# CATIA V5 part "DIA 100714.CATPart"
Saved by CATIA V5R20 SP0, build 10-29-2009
Part number: DIA 100714
Revision: ANY
Definition: UNKNOWN
Nomenclature: DIA 100714
Source: Unknown
Bounding box of the stored display mesh (mm): x -5.35 to 5.35, y -17 to 0, z -5.35 to 5.35
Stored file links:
  C:\Users\Utente\Desktop\IO LAVORO\3D X SITO CF\CUMSA\3D files FA\FA 200712-21\DIA 100714.CATPart
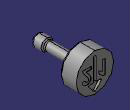
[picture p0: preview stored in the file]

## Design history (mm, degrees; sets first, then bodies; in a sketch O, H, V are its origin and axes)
Body1 "Cortar-Extruir2" (main body)
  Solid1: solid without history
